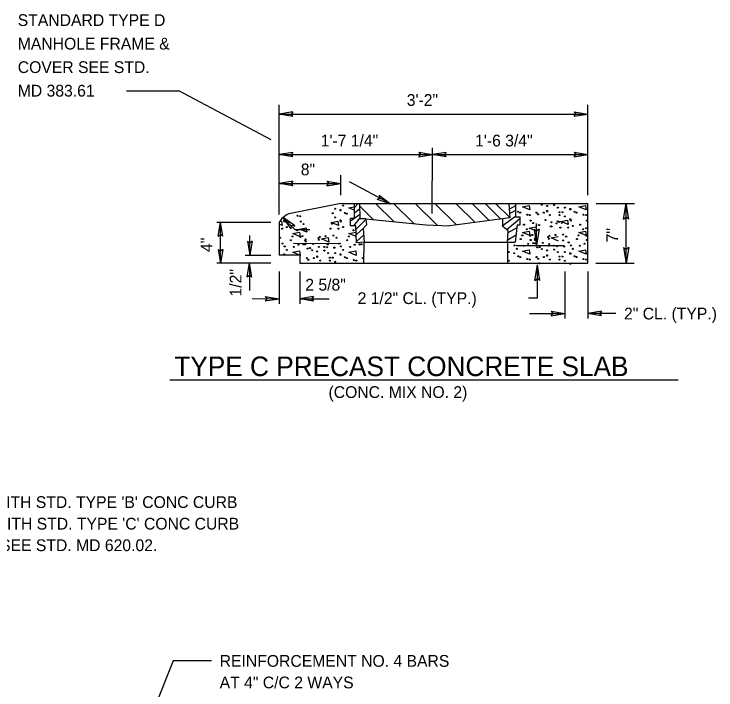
# Model space of a CAD drawing. Extents: x 4.74 to 11.91, y -5.26 to 4.54.
# Drawn here: x 7.673 to 11.256, y 1.095 to 4.543 of the extents above; entities that cross this region are included whole.
import ezdxf

# ---------------------------------------------------------------- set-up
doc = ezdxf.new("R2010")
doc.units = 0
for name, color, linetype in [('DETL-DIMS', 7, 'Continuous'), ('DETL-LINE', 7, 'Continuous'), ('DETL-NOTE', 7, 'Continuous'), ('DETL-PATT', 7, 'Continuous'), ('DETL-TITL', 7, 'Continuous')]:
    doc.layers.add(name, color=color, linetype=linetype)

msp = doc.modelspace()

# ---------------------------------------------------------------- linework, layer by layer
at = {"layer": 'DETL-DIMS'}
for p, q in [((8.2468, 4.1517), (8.5145, 4.1517)), ((8.9847, 3.9006), (8.5145, 4.1517)), ((9.0253, 3.5208), (9.0253, 4.0791)), ((10.602, 3.6187), (10.602, 4.0791)), ((9.0953, 4.044), (9.0253, 4.0326)), ((9.0953, 4.0206), (9.0253, 4.0326)), ((9.0253, 4.0326), (10.602, 4.0326)), ((9.0953, 4.044), (9.0865, 4.0323)), ((9.0953, 4.0206), (9.0865, 4.0323)), ((10.532, 4.0445), (10.602, 4.0326)), ((10.532, 4.0445), (10.5407, 4.0328)), ((10.532, 4.0212), (10.5407, 4.0328)), ((10.532, 4.0212), (10.602, 4.0326)), ((9.0953, 3.837), (9.0253, 3.8257)), ((9.0953, 3.837), (9.0865, 3.8254)), ((9.7382, 3.8376), (9.8082, 3.8257)), ((9.7382, 3.8376), (9.747, 3.8259)), ((9.807, 3.5245), (9.8083, 3.86)), ((9.8782, 3.837), (9.8082, 3.8257)), ((9.8782, 3.837), (9.8695, 3.8254)), ((10.532, 3.8376), (10.602, 3.8257)), ((10.532, 3.8376), (10.5407, 3.8259)), ((9.0953, 3.8137), (9.0253, 3.8257)), ((9.0253, 3.8257), (9.8082, 3.8257)), ((9.0953, 3.8137), (9.0865, 3.8254)), ((9.7382, 3.8143), (9.747, 3.8259)), ((9.7382, 3.8143), (9.8082, 3.8257)), ((9.8782, 3.8137), (9.8082, 3.8257)), ((9.8082, 3.8257), (10.602, 3.8257)), ((9.8782, 3.8137), (9.8695, 3.8254)), ((10.532, 3.8143), (10.5407, 3.8259)), ((10.532, 3.8143), (10.602, 3.8257)), ((9.34, 3.6187), (9.34, 3.7205)), ((9.0953, 3.6898), (9.0253, 3.6785)), ((9.0953, 3.6665), (9.0253, 3.6785)), ((9.0253, 3.6785), (9.34, 3.6785)), ((9.0953, 3.6898), (9.0865, 3.6782)), ((9.0953, 3.6665), (9.0865, 3.6782)), ((9.27, 3.6671), (9.2788, 3.6787)), ((9.27, 3.6671), (9.34, 3.6785)), ((9.2701, 3.6904), (9.34, 3.6785)), ((9.2701, 3.6904), (9.2788, 3.6787)), ((9.5935, 3.5753), (9.3852, 3.6867)), ((9.5263, 3.598), (9.5395, 3.6042)), ((9.5263, 3.598), (9.5935, 3.5753)), ((9.5373, 3.6186), (9.5935, 3.5753)), ((9.5373, 3.6186), (9.5395, 3.6042)), ((10.6437, 3.577), (10.8397, 3.577)), ((10.784, 3.497), (10.7973, 3.577)), ((10.7973, 3.2714), (10.7973, 3.577)), ((10.8107, 3.497), (10.7973, 3.577)), ((8.9836, 3.4792), (8.708, 3.4792)), ((8.7146, 3.4092), (8.7265, 3.4792)), ((8.7265, 3.2714), (8.7265, 3.4792)), ((8.7379, 3.4091), (8.7265, 3.4792)), ((9.0872, 3.4476), (9.0463, 3.5055)), ((9.1038, 3.464), (9.0463, 3.5055)), ((9.0463, 3.5055), (9.1068, 3.4445)), ((10.784, 3.497), (10.7973, 3.507)), ((10.8107, 3.497), (10.7973, 3.507)), ((9.0872, 3.4476), (9.0894, 3.462)), ((9.1038, 3.464), (9.0894, 3.462)), ((9.1068, 3.4445), (9.1817, 3.4445)), ((10.3269, 3.4453), (10.3402, 3.3653)), ((10.3269, 3.4453), (10.3402, 3.4353)), ((10.3402, 3.3653), (10.3402, 3.475)), ((10.3535, 3.4453), (10.3402, 3.3653)), ((10.3535, 3.4453), (10.3402, 3.4353)), ((8.7146, 3.4092), (8.7263, 3.4179)), ((8.7379, 3.4091), (8.7263, 3.4179)), ((8.8755, 3.3135), (8.8755, 3.4129)), ((8.8642, 3.3836), (8.8755, 3.3135)), ((8.8642, 3.3836), (8.8758, 3.3748)), ((8.8875, 3.3835), (8.8755, 3.3135)), ((8.8875, 3.3835), (8.8758, 3.3748)), ((8.7152, 3.3415), (8.7265, 3.2714)), ((8.7152, 3.3415), (8.7268, 3.3327)), ((8.7385, 3.3414), (8.7265, 3.2714)), ((8.7385, 3.3414), (8.7268, 3.3327)), ((10.784, 3.3514), (10.7973, 3.2714)), ((10.784, 3.3514), (10.7973, 3.3414)), ((10.8107, 3.3514), (10.7973, 3.2714)), ((10.8107, 3.3514), (10.7973, 3.3414)), ((8.8517, 3.3136), (8.9836, 3.3131)), ((8.9836, 3.2714), (8.708, 3.2714)), ((8.8634, 3.2015), (8.8754, 3.2714)), ((8.8867, 3.2014), (8.8754, 3.2714)), ((8.8754, 3.2714), (8.8754, 3.133)), ((10.3307, 3.1833), (10.344, 3.2633)), ((10.344, 3.0934), (10.344, 3.2633)), ((10.3573, 3.1833), (10.344, 3.2633)), ((10.6425, 3.2714), (10.8385, 3.2714)), ((9.0253, 3.2297), (9.0253, 3.0648)), ((9.1315, 3.2297), (9.1315, 3.0648)), ((10.4837, 3.2297), (10.4837, 2.9894)), ((10.6008, 3.2297), (10.6008, 2.9904)), ((8.8634, 3.2015), (8.8751, 3.2102)), ((8.8867, 3.2014), (8.8751, 3.2102)), ((10.3307, 3.1833), (10.344, 3.1933)), ((10.3573, 3.1833), (10.344, 3.1933)), ((8.8881, 3.0911), (9.0253, 3.0905)), ((8.9552, 3.0792), (8.964, 3.0908)), ((8.9552, 3.0792), (9.0253, 3.0905)), ((8.9553, 3.1025), (9.0253, 3.0905)), ((8.9553, 3.1025), (8.964, 3.0908)), ((9.2015, 3.1019), (9.1315, 3.0905)), ((9.2015, 3.0786), (9.1315, 3.0905)), ((9.1315, 3.0905), (9.2813, 3.0905)), ((9.2015, 3.1019), (9.1928, 3.0903)), ((9.2015, 3.0786), (9.1928, 3.0903)), ((10.344, 3.0934), (10.2981, 3.0934)), ((10.3046, 3.0148), (10.4837, 3.0148)), ((10.4137, 3.0265), (10.4837, 3.0148)), ((10.4137, 3.0265), (10.4225, 3.0148)), ((10.4137, 3.0032), (10.4837, 3.0148)), ((10.4137, 3.0032), (10.4225, 3.0148)), ((10.6708, 3.0265), (10.6008, 3.0148)), ((10.6708, 3.0032), (10.6008, 3.0148)), ((10.7447, 3.0148), (10.6008, 3.0148)), ((10.6708, 3.0265), (10.6621, 3.0148)), ((10.6708, 3.0032), (10.6621, 3.0148)), ((8.4854, 1.2433), (8.3009, 0.7888)), ((8.6806, 1.2433), (8.4854, 1.2433))]:
    msp.add_line(p, q, dxfattribs=at)
at = {"layer": 'DETL-LINE'}
for p, q in [((9.34, 3.577), (9.0747, 3.5235)), ((9.34, 3.577), (10.602, 3.577)), ((9.4103, 3.5002), (9.4103, 3.577)), ((9.4356, 3.577), (9.4373, 3.4986)), ((10.1989, 3.577), (10.2032, 3.5031)), ((10.2332, 3.577), (10.233, 3.5082)), ((10.6008, 3.2714), (10.602, 3.577)), ((9.0253, 3.4792), (9.0253, 3.3125)), ((9.4103, 3.5002), (9.3899, 3.5003)), ((9.3899, 3.4627), (9.3899, 3.5003)), ((9.468, 3.4986), (9.4373, 3.4986)), ((9.468, 3.4986), (9.4711, 3.4674)), ((9.468, 3.4986), (9.7755, 3.4681)), ((10.2032, 3.5031), (9.8965, 3.4621)), ((10.1685, 3.4595), (10.1685, 3.4986)), ((10.233, 3.5082), (10.2567, 3.5081)), ((10.2567, 3.468), (10.2567, 3.5081)), ((9.4168, 3.4625), (9.3899, 3.4627)), ((9.421, 3.3754), (9.4168, 3.4625)), ((9.4711, 3.4674), (9.4547, 3.4494)), ((9.4547, 3.4494), (9.4594, 3.3783)), ((9.7755, 3.4681), (9.8965, 3.4621)), ((10.1958, 3.4369), (10.1685, 3.4595)), ((10.2408, 3.4681), (10.2309, 3.3783)), ((10.2408, 3.4681), (10.2567, 3.468)), ((10.1913, 3.3783), (10.1958, 3.4369)), ((9.1, 3.3734), (9.3414, 3.3727)), ((9.4594, 3.3783), (9.421, 3.3754)), ((9.4589, 3.2714), (9.4594, 3.3783)), ((9.4594, 3.3783), (10.1913, 3.3783)), ((10.1913, 3.3783), (10.2309, 3.3783)), ((10.1913, 3.3783), (10.1913, 3.2714)), ((10.2362, 3.3629), (10.4831, 3.3622)), ((9.1317, 3.3125), (9.0253, 3.3125)), ((9.1317, 3.3125), (9.1315, 3.2714)), ((9.1315, 3.2714), (10.6008, 3.2714))]:
    msp.add_line(p, q, dxfattribs=at)
msp.add_arc((9.1138, 3.4302), 0.1011, 112.7354, 151.0573, dxfattribs=at)
at = {"layer": 'DETL-PATT'}
for p, q in [((9.4103, 3.5551), (9.4297, 3.577)), ((9.506, 3.4948), (9.4359, 3.5649)), ((9.6105, 3.4845), (9.518, 3.577)), ((9.7127, 3.4743), (9.6101, 3.577)), ((9.8319, 3.4653), (9.7202, 3.577)), ((9.9306, 3.4667), (9.8204, 3.577)), ((10.0261, 3.4795), (9.9285, 3.577)), ((10.0985, 3.4891), (10.0106, 3.577)), ((10.1568, 3.4969), (10.0767, 3.577)), ((10.2032, 3.5046), (10.1307, 3.577)), ((10.2331, 3.5639), (10.2018, 3.5475)), ((10.268, 3.5595), (10.3025, 3.5662)), ((10.3055, 3.5435), (10.268, 3.5595)), ((10.3025, 3.5662), (10.3055, 3.5435)), ((10.5552, 3.5595), (10.5897, 3.5662)), ((10.5927, 3.5435), (10.5552, 3.5595)), ((10.5897, 3.5662), (10.5927, 3.5435)), ((9.4369, 3.5189), (9.3899, 3.4865)), ((9.4363, 3.5468), (9.4103, 3.5262)), ((10.233, 3.5401), (10.203, 3.5254)), ((9.0383, 3.4866), (9.0413, 3.4638)), ((9.2911, 3.4799), (9.3256, 3.4866)), ((9.3286, 3.4638), (9.2911, 3.4799)), ((9.3256, 3.4866), (9.3286, 3.4638)), ((9.4372, 3.5024), (9.4052, 3.4626)), ((9.4177, 3.444), (9.4684, 3.4952)), ((10.233, 3.5107), (10.1651, 3.461)), ((10.2567, 3.5003), (10.1874, 3.442)), ((10.464, 3.4853), (10.4985, 3.492)), ((10.5015, 3.4692), (10.464, 3.4853)), ((10.4985, 3.492), (10.5015, 3.4692)), ((9.129, 3.4459), (9.1635, 3.4527)), ((9.1665, 3.4299), (9.129, 3.4459)), ((9.1635, 3.4527), (9.1665, 3.4299)), ((9.419, 3.4168), (9.4574, 3.4524)), ((10.239, 3.4521), (10.1927, 3.4272)), ((10.3019, 3.4513), (10.3364, 3.4581)), ((10.3394, 3.4353), (10.3019, 3.4513)), ((10.3364, 3.4581), (10.3394, 3.4353)), ((9.0951, 3.4231), (9.1295, 3.4299)), ((9.1325, 3.4071), (9.0951, 3.4231)), ((9.1295, 3.4299), (9.1325, 3.4071)), ((9.3823, 3.4231), (9.4168, 3.4299)), ((9.4207, 3.3825), (9.4569, 3.4152)), ((10.1897, 3.3893), (10.2351, 3.4173)), ((10.268, 3.4285), (10.3025, 3.4353)), ((10.3055, 3.4125), (10.268, 3.4285)), ((10.3025, 3.4353), (10.3055, 3.4125)), ((10.4153, 3.401), (10.4497, 3.4077)), ((10.5552, 3.4285), (10.5897, 3.4353)), ((10.5927, 3.4125), (10.5552, 3.4285)), ((10.5897, 3.4353), (10.5927, 3.4125)), ((9.2424, 3.3955), (9.2768, 3.4023)), ((9.2798, 3.3795), (9.2424, 3.3955)), ((9.2768, 3.4023), (9.2798, 3.3795)), ((10.4527, 3.3849), (10.4153, 3.401)), ((9.0951, 3.3277), (9.1295, 3.3345)), ((9.3823, 3.3277), (9.4168, 3.3345)), ((9.4168, 3.3345), (9.4198, 3.3117)), ((10.268, 3.3331), (10.3025, 3.3399)), ((10.3055, 3.3171), (10.268, 3.3331)), ((10.3025, 3.3399), (10.3055, 3.3171)), ((10.5552, 3.3331), (10.5897, 3.3399)), ((10.5927, 3.3171), (10.5552, 3.3331)), ((10.5897, 3.3399), (10.5927, 3.3171)), ((9.4198, 3.3117), (9.3823, 3.3277))]:
    msp.add_line(p, q, dxfattribs=at)
for points in [[(9.3823, 3.5541), (9.408, 3.5591)], [(9.408, 3.5431), (9.3823, 3.5541)], [(9.0323, 3.4854), (9.0383, 3.4866)], [(9.0413, 3.4638), (9.0253, 3.4707)], [(10.5892, 3.4513), (10.6015, 3.4537)], [(10.6015, 3.446), (10.5892, 3.4513)], [(9.4195, 3.4072), (9.3823, 3.4231)], [(9.1295, 3.3345), (9.1325, 3.3117)], [(9.1306, 3.3125), (9.0951, 3.3277)]]:
    msp.add_lwpolyline(points, dxfattribs=at)
for centre in [(9.3117, 3.5497), (9.3528, 3.566), (10.367, 3.57), (10.3935, 3.5636), (10.4295, 3.5679), (10.4486, 3.5551), (10.4847, 3.5551), (10.5122, 3.5488), (10.5122, 3.5467), (9.1199, 3.5137), (9.1326, 3.5115), (9.299, 3.5264), (9.3393, 3.5434), (9.3393, 3.5412), (9.3605, 3.5285), (9.3711, 3.5243), (10.2462, 3.5339), (10.2568, 3.5297), (10.2928, 3.5191), (10.3055, 3.517), (10.3395, 3.5297), (10.348, 3.5212), (10.3765, 3.5297), (10.3935, 3.5382), (10.3935, 3.536), (10.4083, 3.517), (10.4571, 3.5318), (10.4571, 3.517), (10.472, 3.5318), (10.4847, 3.5106), (10.5334, 3.5339), (10.544, 3.5297), (10.5801, 3.5191), (10.5928, 3.517), (9.0521, 3.4903), (9.0542, 3.484), (9.1369, 3.484), (9.3117, 3.5052), (9.3393, 3.4903), (9.3414, 3.484), (10.3098, 3.4894), (10.3225, 3.4767), (10.385, 3.4915), (10.4168, 3.4809), (10.4422, 3.4746), (10.4484, 3.4852), (10.4543, 3.4827), (10.4685, 3.4782), (10.5122, 3.4957), (10.5143, 3.4894), (10.597, 3.4894), (9.0415, 3.448), (9.0648, 3.4564), (9.103, 3.4628), (9.1178, 3.4395), (9.1496, 3.4712), (9.2884, 3.448), (9.2955, 3.4728), (9.3287, 3.448), (9.352, 3.4564), (9.405, 3.4395), (10.2759, 3.4682), (10.2907, 3.4449), (10.3522, 3.4661), (10.4126, 3.4597), (10.4168, 3.4597), (10.4613, 3.4534), (10.5016, 3.4534), (10.525, 3.4618), (10.5631, 3.4682), (10.578, 3.4449), (9.0309, 3.4018), (9.0945, 3.4082), (9.1348, 3.406), (9.1454, 3.4103), (9.2333, 3.406), (9.263, 3.4103), (9.3033, 3.4124), (9.3181, 3.4018), (9.3817, 3.4082), (10.2674, 3.4136), (10.3077, 3.4115), (10.3183, 3.4157), (10.3998, 3.4051), (10.4062, 3.4115), (10.4359, 3.4157), (10.4762, 3.4178), (10.491, 3.4072), (10.5546, 3.4136), (10.5949, 3.4115), (9.0436, 3.3721), (9.086, 3.3891), (9.1242, 3.3657), (9.1496, 3.3679), (9.1581, 3.387), (9.1581, 3.3679), (9.1602, 3.3933), (9.1623, 3.3827), (9.1994, 3.37), (9.2269, 3.3997), (9.229, 3.3912), (9.2736, 3.3679), (9.3308, 3.3721), (9.3733, 3.3891), (9.4114, 3.3657), (9.4368, 3.3679), (9.4453, 3.3679), (10.2589, 3.3945), (10.2971, 3.3712), (10.3098, 3.3902), (10.3225, 3.3733), (10.331, 3.3924), (10.331, 3.3733), (10.3331, 3.3987), (10.3353, 3.3881), (10.3723, 3.3754), (10.402, 3.3966), (10.4041, 3.369), (10.4762, 3.3881), (10.5038, 3.3775), (10.5462, 3.3945), (10.5843, 3.3712), (10.597, 3.3902), (9.0542, 3.3573), (9.0655, 3.3397), (9.1008, 3.3552), (9.1708, 3.3467), (9.1835, 3.3488), (9.1941, 3.3382), (9.2206, 3.3318), (9.229, 3.3552), (9.2566, 3.3552), (9.2566, 3.3361), (9.2715, 3.353), (9.3075, 3.3509), (9.3414, 3.3573), (9.3528, 3.3397), (9.3881, 3.3552), (10.2271, 3.3627), (10.2385, 3.3451), (10.2737, 3.3606), (10.3437, 3.3521), (10.3565, 3.3542), (10.367, 3.3436), (10.3935, 3.3373), (10.402, 3.3606), (10.4295, 3.3606), (10.4295, 3.3415), (10.4444, 3.3585), (10.4804, 3.3563), (10.5143, 3.3627), (10.5257, 3.3451), (10.561, 3.3606), (9.0521, 3.317), (9.1666, 3.2979), (9.2036, 3.2979), (9.2206, 3.3064), (9.2206, 3.3042), (9.2757, 3.3233), (9.2842, 3.3), (9.299, 3.3), (9.3117, 3.3233), (9.3393, 3.317), (9.3393, 3.3149), (9.3605, 3.3021), (9.3711, 3.2979), (9.4538, 3.2979), (10.1974, 3.3287), (10.225, 3.3224), (10.2462, 3.3075), (10.2568, 3.3033), (10.3395, 3.3033), (10.348, 3.2948), (10.3765, 3.3033), (10.3935, 3.3118), (10.3935, 3.3097), (10.4486, 3.3287), (10.4571, 3.3055), (10.472, 3.3055), (10.4847, 3.3287), (10.5122, 3.3224), (10.5122, 3.3203), (10.5334, 3.3075), (10.544, 3.3033), (9.175, 3.2894), (9.2354, 3.2852), (9.2842, 3.2852), (9.3117, 3.2788), (9.4072, 3.2873), (9.4199, 3.2852), (10.1974, 3.2842), (10.2928, 3.2927), (10.3055, 3.2906), (10.354, 3.2711), (10.4083, 3.2906), (10.4571, 3.2906), (10.4847, 3.2842), (10.5122, 3.2694), (10.5801, 3.2927), (10.5928, 3.2906)]:
    msp.add_circle(centre, 0.00262, dxfattribs=at)
at = {"layer": 'DETL-TITL'}
msp.add_line((8.4681, 2.6763), (11.0619, 2.6763), dxfattribs=at)

# ---------------------------------------------------------------- texts
at = {"layer": 'DETL-NOTE'}
for s, p in [('STANDARD TYPE D', (7.6916, 4.4817)), ('MANHOLE FRAME &', (7.6916, 4.3617)), ('COVER SEE STD.', (7.6916, 4.2417)), ('MD 383.61', (7.6916, 4.1217)), ('3\'-2"', (9.6773, 4.0743)), ('1\'-7 1/4"', (9.238, 3.8673)), ('1\'-6 3/4"', (10.0263, 3.8673)), ('8"', (9.1363, 3.7201)), ('2 5/8"', (9.1593, 3.1322)), ('2 1/2" CL. (TYP.)', (9.4265, 3.0634)), ('2" CL. (TYP.)', (10.7863, 2.9848)), ('(CONC. MIX NO. 2)', (9.2778, 2.5843)), ("TYPE 'B' SLAB SHALL BE USED WITH STD. TYPE 'B' CONC CURB", (6.3397, 2.0232)), ("TYPE 'C' SLAB SHALL BE USED WITH STD. TYPE 'C' CONC CURB", (6.3397, 1.9132)), ('FOR STANDARD CURB DETAILS SEE STD. MD 620.02.', (6.3397, 1.8032)), ('REINFORCEMENT NO. 4 BARS', (8.7223, 1.2133)), ('AT 4" C/C 2 WAYS', (8.7223, 1.1033))]:
    msp.add_text(s, height=0.06, dxfattribs=at).set_placement(p)
for s, p in [('7"', (10.7557, 3.3779)), ('4"', (8.6849, 3.329)), ('1/2"', (8.8337, 3.1018))]:
    msp.add_text(s, height=0.06, rotation=90, dxfattribs=at).set_placement(p)
at = {"layer": 'DETL-TITL'}
msp.add_text('TYPE C PRECAST CONCRETE SLAB', height=0.1, dxfattribs=at).set_placement((8.4908, 2.6959))

doc.saveas('drawing.dxf')
